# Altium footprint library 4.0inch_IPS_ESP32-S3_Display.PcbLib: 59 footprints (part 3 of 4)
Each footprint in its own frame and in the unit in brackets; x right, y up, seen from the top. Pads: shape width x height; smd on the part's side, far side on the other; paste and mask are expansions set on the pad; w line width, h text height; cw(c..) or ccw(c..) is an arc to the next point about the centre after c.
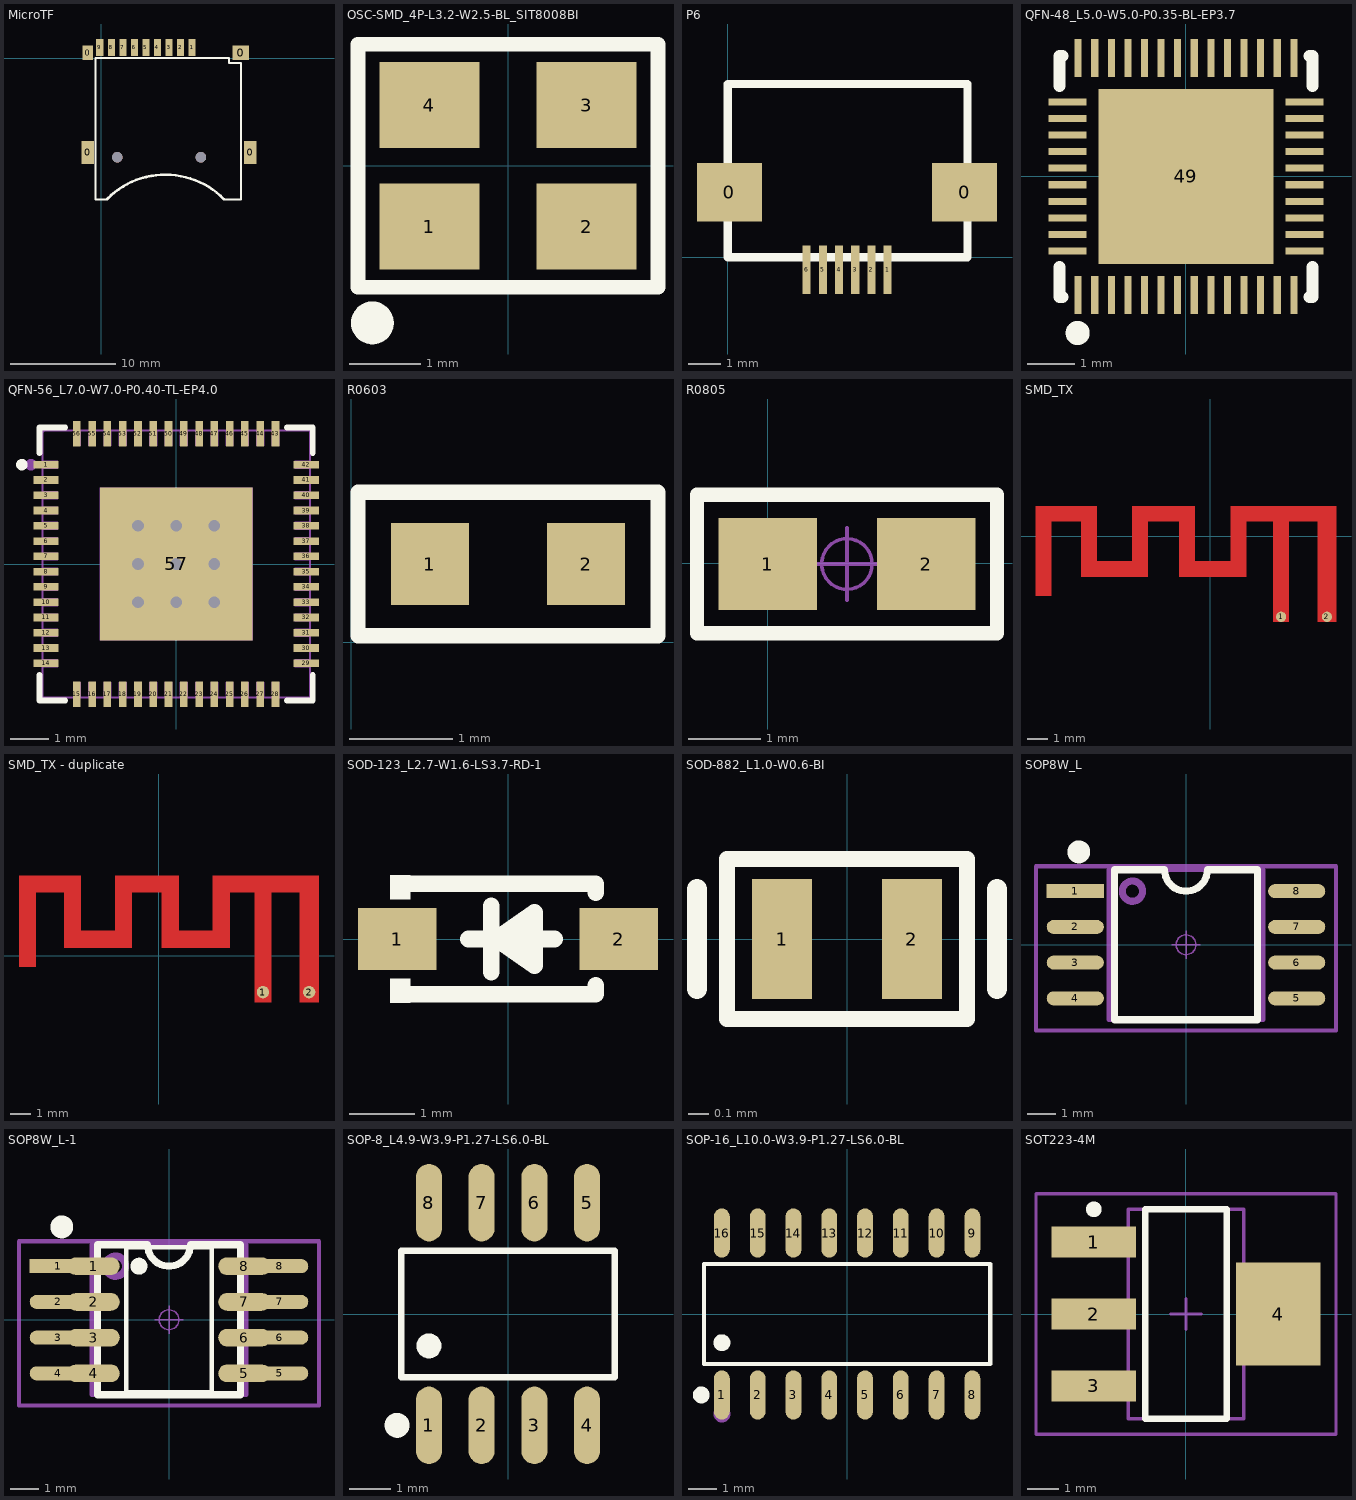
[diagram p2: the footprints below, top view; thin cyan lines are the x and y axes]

## MicroTF [mm]
height 2.65
pads (15):
  rect 1.2x2.2 smd: 0(-1.3,-8.994) 0(14.2,-8.994)
  rect 1x1.4 smd: 0(-1.3,0.526)
  rect 1.6x1.4 smd: 0(13.3,0.526)
  rect 0.7x1.6 smd: 1(8.65,1.026) 2(7.55,1.026) 3(6.45,1.026) 4(5.35,1.026) 5(4.25,1.026) 6(3.15,1.026) 7(2.05,1.026) 8(0.95,1.026) 9(-0.15,1.026)
  round 1 hole 1 unplated: ""(1.52,-9.474) ""(9.5,-9.474)
Top Overlay:
  lines w0.2: 0.563,-13.5 -0.559,-13.5 -0.559,0.026 12.192,0.026 ; 11.709,-13.5 13.335,-13.5 13.335,-0.483
  lines w0.203: 12.192,0.026 12.192,-0.483 13.335,-0.483
  lines w0.254: 0.563,-13.43 cw(c6.113,-18.98) 11.721,-13.489
3D body "User Library-MEM2055-00-190-01-A_revG.STEP": height 1.85, standoff -0.6, extent -1.548,-13.472 14.452,1.778

## OSC-SMD_4P-L3.2-W2.5-BL_SIT8008BI [mm]
pads (4):
  rect 1.4x1.2 smd: 1(-1.1,-0.85) 2(1.1,-0.85) 3(1.1,0.85) 4(-1.1,0.85)
Top Overlay:
  lines w0.203: -2.1,-1.7 -2.1,1.7 2.1,1.7 2.1,-1.7 -2.1,-1.7
  lines w0.3: -1.9,-2.05 ccw(c-1.899,-2.2) -1.897,-2.05
3D body "User Library-OSC2520_SMD_4P_25M.STEP": height 0.55, standoff 0, extent -1.207,-0.944 1.293,1.056

## P6 [mm] "FPC_CONNECTOR"
height 2
pads (8):
  rect 2x1.8 smd: 0(0.051,2.007) 0(7.315,2.007)
  rect 0.25x1.5 smd: 1(4.938,-0.381) 2(4.438,-0.381) 3(3.938,-0.381) 4(3.438,-0.381) 5(2.938,-0.381) 6(2.438,-0.381)
Top Overlay:
  lines w0.254: 0,0 7.4,0 7.4,5.35 0,5.35 0,0
3D body "XB-FPC-CF-5006D0RK-05-NH.stp": height 1.5, standoff -0.05, extent -0.1,-0.5 7.5,5.35

## QFN-48_L5.0-W5.0-P0.35-BL-EP3.7 [mm]
pads (49):
  rect 0.15x0.8 smd paste-100 mask+0.05: 1(-2.275,-2.5) 2(-1.925,-2.5) 3(-1.575,-2.5) 4(-1.225,-2.5) 5(-0.875,-2.5) 6(-0.525,-2.5) 7(-0.175,-2.5) 8(0.175,-2.5) 9(0.525,-2.5) 10(0.875,-2.5) 11(1.225,-2.5) 12(1.575,-2.5) 13(1.925,-2.5) 14(2.275,-2.5) 25(2.275,2.5) 26(1.925,2.5) 27(1.575,2.5) 28(1.225,2.5) 29(0.875,2.5) 30(0.525,2.5) 31(0.175,2.5) 32(-0.175,2.5) 33(-0.525,2.5) 34(-0.875,2.5) 35(-1.225,2.5) 36(-1.575,2.5) 37(-1.925,2.5) 38(-2.275,2.5)
  rect 0.8x0.15 smd paste-100 mask+0.05: 15(2.5,-1.575) 16(2.5,-1.225) 17(2.5,-0.875) 18(2.5,-0.525) 19(2.5,-0.175) 20(2.5,0.175) 21(2.5,0.525) 22(2.5,0.875) 23(2.5,1.225) 24(2.5,1.575) 39(-2.5,1.575) 40(-2.5,1.225) 41(-2.5,0.875) 42(-2.5,0.525) 43(-2.5,0.175) 44(-2.5,-0.175) 45(-2.5,-0.525) 46(-2.5,-0.875) 47(-2.5,-1.225) 48(-2.5,-1.575)
  rect 3.7x3.7 smd paste-100 mask+0.05: 49(0,0)
Top Overlay:
  circle w0.254: c-2.286,-3.302 r0.127
  lines w0.254: -2.667,-1.906 -2.667,-2.54 -2.606,-2.54 ; -2.667,1.906 -2.667,2.54 -2.606,2.54 ; 2.606,-2.54 2.667,-2.54 2.667,-1.906 ; 2.606,2.54 2.667,2.54 2.667,1.906
Top Paste:
  drawing of 49 lines, arcs and shapes, not listed

## QFN-56_L7.0-W7.0-P0.40-TL-EP4.0 [mm]
pads (57):
  rect 0.665x0.2 smd paste-100 mask+0.051: 1(-3.408,2.6) 2(-3.408,2.2) 3(-3.408,1.8) 4(-3.408,1.4) 5(-3.408,1) 6(-3.408,0.6) 7(-3.408,0.2) 8(-3.408,-0.2) 9(-3.408,-0.6) 10(-3.408,-1) 11(-3.408,-1.4) 12(-3.408,-1.8) 13(-3.408,-2.2) 14(-3.408,-2.6) 29(3.408,-2.6) 30(3.408,-2.2) 31(3.408,-1.8) 32(3.408,-1.4) 33(3.408,-1) 34(3.408,-0.6) 35(3.408,-0.2) 36(3.408,0.2) 37(3.408,0.6) 38(3.408,1) 39(3.408,1.4) 40(3.408,1.8) 41(3.408,2.2) 42(3.408,2.6)
  rect 0.2x0.665 smd paste-100 mask+0.051: 15(-2.6,-3.408) 16(-2.2,-3.408) 17(-1.8,-3.408) 18(-1.4,-3.408) 19(-1,-3.408) 20(-0.6,-3.408) 21(-0.2,-3.408) 22(0.2,-3.408) 23(0.6,-3.408) 24(1,-3.408) 25(1.4,-3.408) 26(1.8,-3.408) 27(2.2,-3.408) 28(2.6,-3.408) 43(2.6,3.408) 44(2.2,3.408) 45(1.8,3.408) 46(1.4,3.408) 47(1,3.408) 48(0.6,3.408) 49(0.2,3.408) 50(-0.2,3.408) 51(-0.6,3.408) 52(-1,3.408) 53(-1.4,3.408) 54(-1.8,3.408) 55(-2.2,3.408) 56(-2.6,3.408)
  rect 4x4 smd paste-100 mask+0.051: 57(0,0)
via 0,1 diameter 0.61 hole 0.305
via 0.001,-1 diameter 0.61 hole 0.305
via 0,0 diameter 0.61 hole 0.305
via -1,-1 diameter 0.61 hole 0.305
via 1,-1 diameter 0.61 hole 0.305
via -1,1 diameter 0.61 hole 0.305
via -1,0 diameter 0.61 hole 0.305
via 1,1 diameter 0.61 hole 0.305
via 1,0 diameter 0.61 hole 0.305
Top Overlay:
  circle w0.15: c-4.04,2.6 r0.075
  lines w0.152: -3.576,-2.902 -3.576,-3.576 -2.902,-3.576 ; -3.576,2.903 -3.576,3.576 -2.902,3.576 ; 2.903,-3.576 3.576,-3.576 3.576,-2.902 ; 2.903,3.576 3.576,3.576 3.576,2.903
Top Paste:
  drawing of 57 lines, arcs and shapes, not listed
Mechanical 6:
  circle w0.15: c-3.8,2.6 r0.075
Mechanical 15:
  drawing of 62 lines, arcs and shapes, not listed
3D body "User Library-QFN-56-1.STEP": height 0.83, standoff -0.02, extent -3.51,-3.51 3.51,3.51

## R0603 [mm]
pads (2):
  rect 0.76x0.8 smd: 1(0.766,0.762) 2(2.286,0.762)
Top Overlay:
  lines w0.15: 0.066,0.062 0.066,1.462 2.986,1.462 2.986,0.062 0.066,0.062
3D body "RES0603.STEP": height 0.65, standoff 0.2, extent 0.749,0.348 2.349,1.168

## R0805 [mm]
pads (2):
  rect 1.36x1.27 smd: 1(0.001,-0.01) 2(2.19,-0.01)
Top Overlay:
  lines w0.2: -0.979,-0.965 3.17,-0.965 3.17,0.945 -0.979,0.945 -0.979,-0.965
Mechanical 15:
  circle w0.05: c1.096,-0.01 r0.35
  lines w0.05: 0.596,-0.01 1.596,-0.01 ; 1.096,-0.51 1.096,0.49

## SMD_TX [mm]
pads (2):
  round 0.5 smd mask+0.102: 1(3.467,-3.939)
  round 0.5 smd: 2(5.705,-3.939)
Top Layer:
  region: -0.738,-1.233 -1.494,-1.233 -1.494,0.716
  region: 6.146,0.716 1.019,1.467 6.146,1.467
  region: 6.146,0.716 1.019,0.716 1.019,1.467
  region: -0.738,0.716 -3.794,1.467 -0.738,1.467
  region: -0.738,0.716 -3.794,0.716 -3.794,1.467
  region: -0.738,-1.233 -1.494,0.716 -0.738,0.716
  region: -3.039,-1.233 -3.794,0.716 -3.039,0.716
  region: -3.039,-1.233 -3.794,-1.233 -3.794,0.716
  region: 1.77,-1.988 -1.494,-1.233 1.77,-1.233
  region: 1.77,-1.988 -1.494,-1.988 -1.494,-1.233
  region: -5.539,0.716 -8.495,1.467 -5.539,1.467
  region: -5.539,0.716 -8.495,0.716 -8.495,1.467
  region: -3.039,-1.988 -6.294,-1.233 -3.039,-1.233
  region: -3.039,-1.988 -6.294,-1.988 -6.294,-1.233
  region: 6.146,-4.189 5.264,0.716 6.146,0.716
  region: 6.146,-4.189 5.264,-4.189 5.264,0.716
  region: 3.845,-4.189 3.09,0.716 3.845,0.716
  region: 3.845,-4.189 3.09,-4.189 3.09,0.716
  region: 1.77,-1.233 1.019,0.716 1.77,0.716
  region: 1.77,-1.233 1.019,-1.233 1.019,0.716
  region: -5.539,-1.233 -6.294,0.716 -5.539,0.716
  region: -5.539,-1.233 -6.294,-1.233 -6.294,0.716
  region: -7.74,-2.913 -8.495,0.716 -7.74,0.716
  region: -7.74,-2.913 -8.495,-2.913 -8.495,0.716

## SMD_TX - duplicate [mm]
pads (2):
  round 0.6 smd mask+0.102: 1(5.038,-1.767)
  round 0.6 smd: 2(7.278,-1.767)
Top Layer:
  rectangle: -6.777,3.053 -3.777,3.883
  rectangle: -6.777,-0.557 -5.947,3.883
  rectangle: -4.607,0.383 -3.777,3.883
  rectangle: -4.607,0.383 -1.307,1.213
  rectangle: -2.137,0.383 -1.307,3.883
  rectangle: -2.137,3.053 0.963,3.883
  rectangle: 0.133,0.383 0.963,3.883
  rectangle: 0.133,0.383 3.433,1.213
  rectangle: 2.603,0.383 3.433,3.883
  rectangle: 2.603,3.053 7.753,3.883
  rectangle: 4.623,-2.267 5.453,3.883
  rectangle: 6.803,-2.267 7.753,3.883

## SOD-123_L2.7-W1.6-LS3.7-RD-1 [mm]
pads (2):
  rect 1.2x0.95 smd: 1(-1.7,0) 2(1.7,0)
Top Overlay:
  region: -1.502,-0.977 -1.502,-0.607 -1.806,-0.607 -1.806,-0.977
  region: -1.502,0.977 -1.502,0.607 -1.806,0.607 -1.806,0.977
  region: 0.406,-0.406 0.406,0.406 -0.178,0
  lines w0.254: -1.644,0.849 -1.643,0.85 -1.346,0.85 1.346,0.85 1.346,0.706 ; -1.639,-0.849 -1.638,-0.85 -1.346,-0.85 1.346,-0.85 1.346,-0.706 ; -0.61,0 -0.28,0 ; -0.254,-0.508 -0.254,0.508 ; 0.406,0 0.72,0 ; -0.178,0 0.406,-0.406 0.406,0.406 -0.178,0
3D body "CircuitWorks-SOD123.STEP": height 1.27, standoff 0, extent -2.056,-0.774 1.644,0.826

## SOD-882_L1.0-W0.6-BI [mm]
pads (2):
  rect 0.3x0.6 smd paste+0 mask+0.05: 1(-0.325,0) 2(0.325,0)
Top Overlay:
  lines w0.08: -0.6,-0.4 -0.6,0.4 0.6,0.4 0.6,-0.4 -0.6,-0.4
  lines w0.1: -0.75,-0.25 -0.75,0.25 ; 0.75,-0.25 0.75,0.25

## SOP8W_L [mm] "5.3*8.3*1.8mm（长宽高）"
pads (8):
  rect 2.032x0.5 smd: 1(-3.937,1.905)
  oval 2.032x0.5 smd: 2(-3.937,0.635) 3(-3.937,-0.635) 4(-3.937,-1.905) 5(3.937,-1.905) 6(3.937,-0.635) 7(3.937,0.635) 8(3.937,1.905)
Top Overlay:
  circle w0.5: c-3.81,3.302 r0.155
  lines w0.254: -2.54,-2.667 -2.54,2.667 -0.762,2.667 ccw(c0,2.667) 0.762,2.667 2.54,2.667 2.54,-2.667 -2.54,-2.667
Mechanical 13:
  circle w0.254: c-1.905,1.905 r0.359
  lines w0.15: -2.75,-2.667 2.75,-2.667 2.75,2.667 -2.75,2.667 -2.75,-2.667
Mechanical 15:
  circle w0.05: c0,0 r0.35
  lines w0.05: -0.5,0 0.5,0 ; 0,-0.5 0,0.5
  lines w0.15: -5.334,-3.048 -5.334,2.794 5.334,2.794 5.334,-3.048 -5.334,-3.048
3D body "SOP8W.STEP": height 1.9, standoff 0, extent -3.943,-2.64 3.943,2.64

## SOP8W_L-1 [mm] "5.3*8.3*1.8mm（长宽高）"
pads (16):
  rect 2.032x0.5 smd: 1(-3.937,1.905)
  oval 1.865x0.63 smd: 1(-2.683,1.905) 2(-2.683,0.635) 3(-2.683,-0.635) 4(-2.683,-1.905) 5(2.682,-1.905) 6(2.682,-0.635) 7(2.682,0.635) 8(2.682,1.905)
  oval 2.032x0.5 smd: 2(-3.937,0.635) 3(-3.937,-0.635) 4(-3.937,-1.905) 5(3.937,-1.905) 6(3.937,-0.635) 7(3.937,0.635) 8(3.937,1.905)
Top Overlay:
  circle w0.3: c-1.069,1.905 r0.15
  circle w0.5: c-3.81,3.302 r0.155
  lines w0.152: -1.521,-2.576 -1.521,2.576 1.521,2.576 1.521,-2.576 -1.521,-2.576
  lines w0.254: -2.54,-2.667 -2.54,2.667 -0.762,2.667 ccw(c0,2.667) 0.762,2.667 2.54,2.667 2.54,-2.667 -2.54,-2.667
Mechanical 13:
  circle w0.254: c-1.905,1.905 r0.359
  lines w0.15: -2.75,-2.667 2.75,-2.667 2.75,2.667 -2.75,2.667 -2.75,-2.667
Mechanical 15:
  circle w0.05: c0,0 r0.35
  lines w0.05: -0.5,0 0.5,0 ; 0,-0.5 0,0.5
  lines w0.15: -5.334,-3.048 -5.334,2.794 5.334,2.794 5.334,-3.048 -5.334,-3.048
3D body "SOP8W.STEP": height 1.9, standoff 0, extent -3.943,-2.64 3.943,2.64

## SOP-8_L4.9-W3.9-P1.27-LS6.0-BL [mm]
pads (8):
  oval 0.63x1.865 smd: 1(-1.905,-2.682) 2(-0.635,-2.682) 3(0.635,-2.682) 4(1.905,-2.682) 5(1.905,2.682) 6(0.635,2.682) 7(-0.635,2.682) 8(-1.905,2.682)
Top Overlay:
  circle w0.3: c-2.672,-2.682 r0.15
  circle w0.3: c-1.905,-0.769 r0.15
  lines w0.152: -2.576,-1.521 2.576,-1.521 2.576,1.521 -2.576,1.521 -2.576,-1.521
3D body "User Library-sop8_model.STEP": height 1.55, standoff -0.01, extent -2.452,-3.111 2.448,2.869

## SOP-16_L10.0-W3.9-P1.27-LS6.0-BL [mm]
pads (16):
  oval 0.56x1.745 smd mask+0.051: 1(-4.445,-2.872) 2(-3.175,-2.872) 3(-1.905,-2.872) 4(-0.635,-2.872) 5(0.635,-2.872) 6(1.905,-2.872) 7(3.175,-2.872) 8(4.445,-2.872) 9(4.445,2.872) 10(3.175,2.872) 11(1.905,2.872) 12(0.635,2.872) 13(-0.635,2.872) 14(-1.905,2.872) 15(-3.175,2.872) 16(-4.445,2.872)
Top Overlay:
  circle w0.3: c-5.177,-2.872 r0.15
  circle w0.3: c-4.445,-1.019 r0.15
  lines w0.152: -5.076,-1.771 5.076,-1.771 5.076,1.771 -5.076,1.771 -5.076,-1.771
Mechanical 6:
  circle w0.3: c-4.445,-3.55 r0.15

## SOT223-4M [mm]
height 2.65
pads (4):
  rect 2.7x1 smd: 1(-2.95,2.3) 2(-2.95,0) 3(-2.95,-2.3)
  rect 2.7x3.3 smd: 4(2.95,0)
Top Overlay:
  circle w0.25: c-2.95,3.35 r0.125
  lines w0.2: -1.3,-3.35 1.3,-3.35 1.3,3.35 -1.3,3.35 -1.3,-3.35
Mechanical 13:
  lines w0.1: -1.85,-3.35 1.85,-3.35 1.85,3.35 -1.85,3.35 -1.85,-3.35
Mechanical 15:
  lines w0.1: -0.5,0 0.5,0 ; 0,-0.5 0,0.5 ; -4.8,-3.85 4.8,-3.85 4.8,3.85 -4.8,3.85 -4.8,-3.85
3D body "SOT223.STEP": height 1.6, standoff -0.05, extent -3.531,-3.25 3.469,3.25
